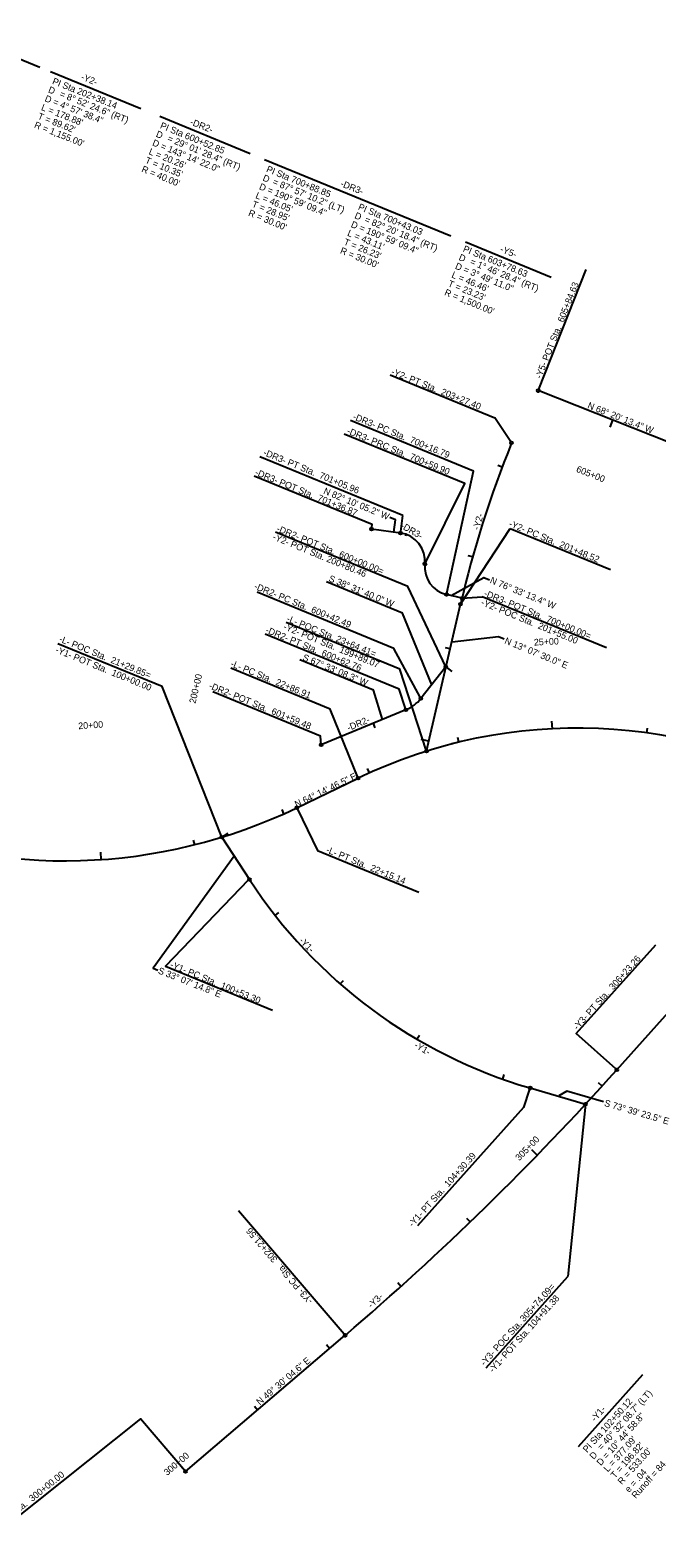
# Model space of a CAD drawing. Extents: x 2090177 to 2092717, y 863117 to 864817.
# Drawn here: x 2091049 to 2091711, y 863141 to 864733 of the extents above; entities that cross this region are included whole.
import ezdxf

# ---------------------------------------------------------------- set-up
doc = ezdxf.new("R2010")
doc.units = 0
for name, color, linetype in [('Prop Horizontal Alignment', 7, 'Continuous'), ('Prop Horizontal Alignment Curve and Spiral Data', 7, 'Continuous'), ('Prop Horizontal Alignment Direction Label', 7, 'Continuous'), ('Prop Horizontal Alignment Point', 7, 'Continuous'), ('Prop Horizontal Alignment Station Label', 7, 'Continuous'), ('Prop Horizontal Alignment Tick Label', 7, 'Continuous'), ('Prop Horizontal Alignment Tick Large', 7, 'Continuous'), ('Prop Horizontal Alignment Tick Small', 7, 'Continuous')]:
    doc.layers.add(name, color=color, linetype=linetype)

msp = doc.modelspace()

# ---------------------------------------------------------------- linework, layer by layer
at = {"layer": 'Prop Horizontal Alignment'}
for p, q in [((2091668.6, 863635.4), (2092320, 864363.2)), ((2091755.4, 864285.3), (2091585.5, 864352.7)), ((2091755.4, 864285.3), (2091585.5, 864352.7)), ((2091440.1, 864202.3), (2091409.5, 864206.5)), ((2091505.1, 864133.4), (2091488.7, 864137.4)), ((2091467.4, 863971.9), (2091503.6, 864127.1)), ((2091488.1, 864060.9), (2091461.7, 864027.6)), ((2091445.6, 864015.6), (2091356.3, 863978.6)), ((2091330.7, 863912.2), (2091395.4, 863943.4)), ((2091251.4, 863881), (2091280.5, 863836.4)), ((2091577, 863616.2), (2091635.5, 863599)), ((2091213, 863211), (2091381.5, 863354.9))]:
    msp.add_line(p, q, dxfattribs=at)
for centre, radius, start, end in [((2092628.4, 863864.9), 1155, 158.0015, 166.875), ((2091436, 864172.6), 30, 354.2153, 82.1681), ((2091495.7, 864166.5), 30, 174.2153, 256.5537), ((2091430.4, 864052.5), 40, 292.4477, 321.4722), ((2091627, 863463.3), 533, 59.4206, 115.7537), ((2091085.2, 864421.1), 565, 247.6724, 295.7537), ((2091726.9, 864127.6), 533, 213.1208, 253.6565), ((2089433.2, 865636.1), 3000, 310.4987, 318.1706)]:
    msp.add_arc(centre, radius, start, end, dxfattribs=at)
at = {"layer": 'Prop Horizontal Alignment Curve and Spiral Data'}
for p, q in [((2090964.2, 864733.5), (2091059.1, 864694.5)), ((2091070.5, 864689.8), (2091165.8, 864650.6)), ((2091185.8, 864642.5), (2091281.1, 864603.3)), ((2091296.4, 864597), (2091493.4, 864516.1)), ((2091508.8, 864509.8), (2091599.2, 864472.7)), ((2091628.3, 863237.6), (2091696.2, 863313.5))]:
    msp.add_line(p, q, dxfattribs=at)
for points in [[(2091493.5, 864136.2), (2091528, 864155.4), (2091534, 864153)], [(2091494.5, 864087.3), (2091543.7, 864093), (2091549.7, 864090.6)]]:
    msp.add_lwpolyline(points, dxfattribs=at)
at = {"layer": 'Prop Horizontal Alignment Direction Label'}
msp.add_lwpolyline([(2091654.4, 863601.4), (2091615.9, 863612.7), (2091607.2, 863607.7)], dxfattribs=at)
at = {"layer": 'Prop Horizontal Alignment Station Label'}
for p, q in [((2091586.1, 864354.1), (2091636.4, 864480.7)), ((2091429.3, 864369.5), (2091539.8, 864324.1)), ((2091556.7, 864298.8), (2091539.8, 864324.1)), ((2091440.3, 864203.8), (2091442.7, 864220.8)), ((2091503.6, 864127.1), (2091556.1, 864207.2)), ((2091556.1, 864207.2), (2091661.8, 864163.8)), ((2091505.1, 864133.4), (2091526.3, 864134.9)), ((2091635.5, 863599), (2091616.7, 863416.9)), ((2091380.5, 863356), (2091269.1, 863486.4)), ((2091530.6, 863320.7), (2091616.7, 863416.9))]:
    msp.add_line(p, q, dxfattribs=at)
for points in [[(2091489.1, 864138.8), (2091517.2, 864267.7), (2091387.3, 864321.1)], [(2091466.5, 864170.9), (2091508, 864254.5), (2091380.5, 864306.8)], [(2091442.7, 864220.8), (2091291.5, 864282.9)], [(2091409.5, 864206.5), (2091410.1, 864211.2), (2091285.6, 864262.3)], [(2091433, 864203.3), (2091434.8, 864216.3), (2091428.9, 864218.7)], [(2091488.1, 864060.9), (2091447.7, 864145.9), (2091308, 864203.3)], [(2091461, 864028.9), (2091433.1, 864080.4), (2091288.5, 864139.8)], [(2091473.2, 864042.1), (2091442.3, 864117.6), (2091361.8, 864150.7)], [(2091657.6, 864081), (2091526.3, 864134.9)], [(2091467.4, 863971.9), (2091439.3, 864058.6), (2091319.2, 864107.9)], [(2091445.2, 864017), (2091438.8, 864037.4), (2091297.2, 864095.6)], [(2091251.4, 863881), (2091188.3, 864040.1), (2091078, 864085.4)], [(2091395.4, 863943.4), (2091365.9, 864016.4), (2091260.9, 864059.5)], [(2091420.9, 864005.3), (2091411.5, 864036.2), (2091333.6, 864068.2)], [(2091356.3, 863978.6), (2091355.5, 863987.8), (2091241.8, 864034.5)], [(2091331.4, 863910.8), (2091352.5, 863867), (2091459.3, 863823.1)], [(2091264.5, 863861.1), (2091178.9, 863742.7), (2091183.8, 863740.7)], [(2091279.3, 863835.6), (2091191.7, 863744.9), (2091304.7, 863698.5)], [(2091667.5, 863636.4), (2091625.8, 863673.6), (2091709.9, 863767.5)], [(2091576.5, 863614.8), (2091570, 863595.6), (2091457.9, 863470.4)], [(2091213, 863211), (2091165.3, 863266.8), (2091026.2, 863155.8)]]:
    msp.add_lwpolyline(points, dxfattribs=at)
for centre in [(2091585.5, 864352.7), (2091557.5, 864297.5), (2091409.5, 864206.5), (2091440.1, 864202.3), (2091465.9, 864169.6), (2091488.7, 864137.4), (2091503.6, 864127.1), (2091505.1, 864133.4), (2091488.1, 864060.9), (2091461.7, 864027.6), (2091445.6, 864015.6), (2091356.3, 863978.6), (2091467.4, 863971.9), (2091395.4, 863943.4), (2091330.7, 863912.2), (2091251.4, 863881), (2091251.4, 863881), (2091280.5, 863836.4), (2091668.6, 863635.4), (2091577, 863616.2), (2091635.5, 863599), (2091381.5, 863354.9), (2091213, 863211)]:
    msp.add_circle(centre, 1.5, dxfattribs=at)
at = {"layer": 'Prop Horizontal Alignment Tick Large'}
for p, q in [((2091664.2, 864321.5), (2091661.2, 864314.1)), ((2091505.1, 864133.4), (2091504.3, 864130.3)), ((2091488.1, 864060.9), (2091494.4, 864055.9)), ((2091600.5, 863995.6), (2091600.1, 864003.6)), ((2091469.9, 863982.5), (2091462.1, 863984.3)), ((2091501.7, 863981.4), (2091493.9, 863979.5)), ((2091251.4, 863881), (2091258.1, 863885.4)), ((2091124, 863857.4), (2091123.5, 863865.4)), ((2091584.5, 863545.3), (2091578.8, 863550.8)), ((2091213, 863211), (2091207.8, 863217.1))]:
    msp.add_line(p, q, dxfattribs=at)
at = {"layer": 'Prop Horizontal Alignment Tick Small'}
for p, q in [((2091547.5, 864272), (2091542.9, 864273.7)), ((2091445.9, 864200.9), (2091445.2, 864199)), ((2091516.4, 864177), (2091511.6, 864178.3)), ((2091492.6, 864079.9), (2091487.7, 864081)), ((2091411.2, 864001.3), (2091413.1, 863996.7)), ((2091700.2, 863991.2), (2091700.9, 863996.2)), ((2091501.7, 863981.4), (2091500.5, 863986.2)), ((2091407.2, 863948.9), (2091405.2, 863953.5)), ((2091317, 863905.8), (2091315, 863910.3)), ((2091222.7, 863873), (2091221.5, 863877.9)), ((2091307.7, 863798.5), (2091311.7, 863801.5)), ((2091376.5, 863726), (2091379.8, 863729.8)), ((2091457.5, 863667.7), (2091460.1, 863672)), ((2091548.1, 863625.6), (2091549.7, 863630.3)), ((2091653, 863618.1), (2091649.3, 863621.5)), ((2091513.6, 863474.7), (2091510.2, 863478.3)), ((2091440.4, 863406.6), (2091437.1, 863410.3)), ((2091365.1, 863340.9), (2091361.8, 863344.7)), ((2091289, 863275.9), (2091285.8, 863279.7))]:
    msp.add_line(p, q, dxfattribs=at)

# ---------------------------------------------------------------- texts
at = {"layer": 'Prop Horizontal Alignment Curve and Spiral Data'}
for s, rotation, p in [('PI Sta 202+38.14', 338.317, (2091071.6, 864676.9)), ('-Y2-', 338.2396, (2091101.9, 864681.4)), ('D = 4%%d 57\' 38.4"', 338.317, (2091063.6, 864658.6)), ('D', 338.317, (2091067.3, 864667.9)), ('= 8%%d 52\' 24.6" (RT)', 338.317, (2091079.3, 864663.4)), ("T = 89.62'", 338.317, (2091056.2, 864640)), ("L = 178.88'", 338.317, (2091059.9, 864649.3)), ("R = 1,155.00'", 338.317, (2091052.5, 864630.7)), ('PI Sta 600+52.85', 337.6724, (2091185.5, 864630.1)), ('-DR2-', 338.2396, (2091217.1, 864634)), ('D = 143%%d 14\' 22.0"', 337.6724, (2091177.3, 864611.9)), ('D', 337.665, (2091181.1, 864621.1)), ('= 29%%d 01\' 28.4" (RT)', 337.6724, (2091193.1, 864616.5)), ("T = 10.35'", 337.6724, (2091169.7, 864593.4)), ("L = 20.26'", 337.6724, (2091173.5, 864602.6)), ("R = 40.00'", 337.6724, (2091165.9, 864584.1)), ('PI Sta 700+88.85', 337.6659, (2091297.7, 864584.1)), ('D = 190%%d 59\' 09.4"', 337.6659, (2091290.1, 864565.6)), ('D', 337.6659, (2091293.9, 864574.8)), ('= 87%%d 57\' 10.2" (LT)', 337.6659, (2091304.4, 864570.7)), ('-DR3-', 338.2396, (2091376, 864568.8)), ("T = 28.95'", 337.6659, (2091282.5, 864547.1)), ("L = 46.05'", 337.6659, (2091286.3, 864556.3)), ("R = 30.00'", 337.6659, (2091278.7, 864537.8)), ('D', 337.6659, (2091390.9, 864535)), ('PI Sta 700+43.03', 337.6659, (2091394.7, 864544.2)), ('= 82%%d 20\' 18.4" (RT)', 337.6659, (2091401.4, 864530.8)), ("L = 43.11'", 337.6659, (2091383.3, 864516.5)), ('D = 190%%d 59\' 09.4"', 337.6659, (2091387.1, 864525.7)), ("R = 30.00'", 337.6659, (2091375.7, 864498)), ("T = 26.23'", 337.6659, (2091379.5, 864507.2)), ('PI Sta 603+78.63', 337.6724, (2091505.5, 864499.9)), ('-Y5-', 338.2396, (2091544.7, 864499.5)), ('D = 3%%d 49\' 11.0"', 337.6724, (2091497.2, 864481.7)), ('D', 337.6724, (2091501, 864490.9)), ('= 1%%d 46\' 28.4" (RT)', 337.6724, (2091513, 864486.3)), ("L = 46.46'", 337.6724, (2091493.4, 864472.4)), ("R = 1,500.00'", 337.6724, (2091485.9, 864453.9)), ("T = 23.23'", 337.6724, (2091489.6, 864463.2)), ('= 40%%d 32\' 08.7" (LT)', 48.1706, (2091652.6, 863233.1)), ('PI Sta 102+50.12', 48.1706, (2091637.2, 863230.5)), ('-Y1-', 48.7377, (2091645.7, 863263.2)), ('D = 10%%d 44\' 58.8"', 48.1706, (2091651.7, 863216.7)), ("L = 377.09'", 48.1706, (2091659.1, 863210)), ('D', 48.1706, (2091644.2, 863223.3)), ("T = 196.82'", 48.1706, (2091666.6, 863203.3)), ("R = 533.00'", 48.1706, (2091674, 863196.7)), ('e = .04', 48.2242, (2091681.6, 863188.4)), ('Runoff = 84', 48.2242, (2091688.7, 863182))]:
    msp.add_text(s, height=7, rotation=rotation, dxfattribs=at).set_placement(p)
at = {"layer": 'Prop Horizontal Alignment Direction Label'}
for s, rotation, p in [('N 68%%d 20\' 13.4" W', 338.3371, (2091637, 864334.4)), ('N 82%%d 10\' 05.2" W', 337.6724, (2091358.1, 864244.1)), ('S 38%%d 31\' 40.0" W', 337.6724, (2091363.6, 864151.6)), ('N 76%%d 33\' 13.4" W', 337.6724, (2091534, 864149.8)), ('N 13%%d 07\' 30.0" E', 337.6724, (2091549.4, 864085.9)), ('S 67%%d 33\' 08.3" W', 337.6724, (2091336, 864068.3)), ('N 64%%d 14\' 46.5" E', 25.7537, (2091330.4, 863912.2)), ('S 33%%d 07\' 14.8" E', 338.4859, (2091183.3, 863737.4)), ('S 73%%d 39\' 23.5" E', 343.6565, (2091654.8, 863597.3)), ('N 49%%d 30\' 04.6" E', 40.4987, (2091291.4, 863280.8))]:
    msp.add_text(s, height=7, rotation=rotation, dxfattribs=at).set_placement(p)
at = {"layer": 'Prop Horizontal Alignment Point'}
for s, rotation, p in [('-Y2-', 73.0955, (2091522.9, 864204.9)), ('-DR3-', 330.0002, (2091439.5, 864208.1)), ('-DR2-', 22.4477, (2091385.3, 863993.1)), ('-Y1-', 314.5111, (2091332.4, 863771.2)), ('-Y1-', 329.5309, (2091453.9, 863659.5)), ('-Y3-', 42.2145, (2091409.2, 863383.1))]:
    msp.add_text(s, height=7, rotation=rotation, dxfattribs=at).set_placement(p)
at = {"layer": 'Prop Horizontal Alignment Station Label'}
for s, rotation, p in [('-Y5- POT Sta.  605+84.63', 68.3371, (2091588.6, 864364.8)), ('-Y2- PT Sta.  203+27.40', 338.0015, (2091429.6, 864370.1)), ('-DR3- PRC Sta.  700+59.90', 337.6724, (2091382.8, 864307.6)), ('-DR3- PC Sta.  700+16.79', 337.6724, (2091389.1, 864322.7)), ('-DR3- PT Sta.  701+05.96', 337.6724, (2091294.5, 864284.8)), ('-DR3- POT Sta.  701+36.87', 337.6724, (2091285.8, 864263.8)), ('-Y2- POT Sta. 200+80.46', 337.6724, (2091304.4, 864195.7)), ('-DR2- POT Sta.  600+00.00=', 337.6724, (2091308.5, 864204.4)), ('-Y2- PC Sta.  201+48.52', 337.6724, (2091553.9, 864209.6)), ('-DR2- PC Sta.  600+42.49', 337.6724, (2091284.9, 864143.5)), ('-DR3- POT Sta.  700+00.00=', 337.6724, (2091527.6, 864136)), ('-Y2- POC Sta.  201+55.00', 337.6724, (2091524.5, 864126.5)), ('-Y2- POT Sta.  199+89.07', 337.7224, (2091315.7, 864100.8)), ('-L- POC Sta. 23+64.41=', 337.7224, (2091319.2, 864109.3)), ('-L- POC Sta.  21+29.85=', 337.785, (2091078.8, 864087.8)), ('-DR2- PT Sta.  600+62.76', 337.6724, (2091296.9, 864097.3)), ('-Y1- POT Sta.  100+00.00', 337.785, (2091074.9, 864076.4)), ('-L- PC Sta.  22+86.91', 337.6724, (2091259.9, 864061.8)), ('-DR2- POT Sta.  601+59.48', 337.6724, (2091237, 864038.5)), (' -L- PT Sta.  22+15.14', 337.6724, (2091358.4, 863866.2)), ('-Y3- PT Sta.  306+23.26', 48.1706, (2091627, 863676.9)), ('-Y1- PC Sta.  100+53.30', 337.6724, (2091196, 863743.8)), ('-Y1- PT Sta.  104+30.39', 48.1706, (2091452.9, 863468.8)), ('-Y3- PC Sta.  302+21.56', 130.4987, (2091348.1, 863391.5)), ('-Y3- POC Sta. 305+74.09=', 48.0477, (2091528.9, 863322.2)), ('-Y1- POT Sta. 104+91.38', 48.0477, (2091537.8, 863314.8)), ('-Y3- POT Sta.  300+00.00', 38.567, (2091000.9, 863138.9))]:
    msp.add_text(s, height=7, rotation=rotation, dxfattribs=at).set_placement(p)
at = {"layer": 'Prop Horizontal Alignment Tick Label'}
for s, rotation, p in [('605+00', 338.3371, (2091625.1, 864267.2)), ('25+00', 2.8474, (2091581.2, 864083.4)), ('200+00', 76.875, (2091223.5, 864021.8)), ('20+00', 3.9365, (2091099.9, 863995)), ('305+00', 45.8165, (2091565.6, 863538.7)), ('300+00', 40.4987, (2091193.6, 863206.3))]:
    msp.add_text(s, height=7, rotation=rotation, dxfattribs=at).set_placement(p)

doc.saveas('drawing.dxf')
